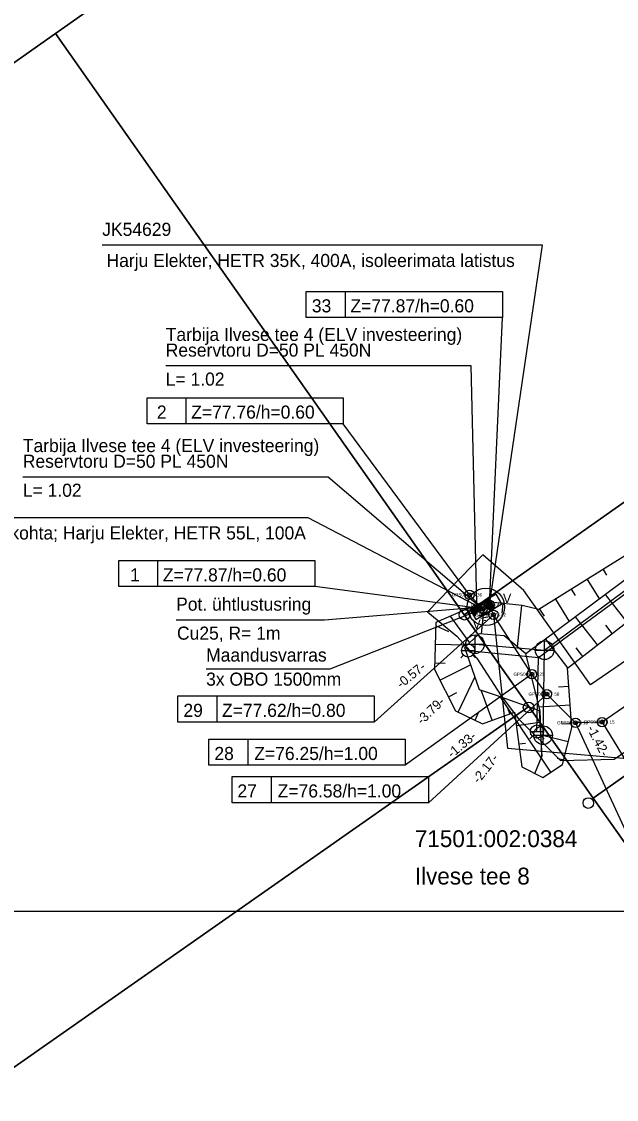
# Model space of a CAD drawing. Extents: x 593727 to 603084, y 6472047 to 6482364.
# Drawn here: x 595964.2 to 595996, y 6473948.9 to 6474006.5 of the extents above; entities that cross this region are included whole.
import ezdxf

# ---------------------------------------------------------------- set-up
doc = ezdxf.new("R2010")
doc.units = 0
for name, color, linetype in [('ELRAJATISMP', 7, 'Continuous'), ('JOONSIDE', 7, 'Continuous'), ('KKAEV', 7, 'Continuous'), ('KOORDPUNKT', 7, 'Continuous'), ('KTRASS', 7, 'Continuous'), ('MOOTKORG-EH2000', 7, 'Continuous'), ('MOOTMPUNKT', 7, 'Continuous'), ('MOOTNR', 7, 'Continuous'), ('MOOTPIIR', 7, 'Continuous'), ('MPKAABEL', 7, 'Continuous'), ('PIIR', 7, 'Continuous'), ('PIIRIMLEITUD', 7, 'Continuous'), ('RELJEEF', 7, 'Continuous'), ('VKAEV', 7, 'Continuous'), ('VORMISTUS', 7, 'Continuous'), ('VTRASS', 7, 'Continuous')]:
    doc.layers.add(name, color=color, linetype=linetype)

msp = doc.modelspace()

# ---------------------------------------------------------------- linework, layer by layer
at = {"layer": 'ELRAJATISMP'}
for p, q in [((595989.191, 6473975.644), (595988.163, 6473975.036)), ((595988.91, 6473975.459), (595988.171, 6473975.022)), ((595988.39, 6473974.652), (595988.931, 6473975.491)), ((595989.559, 6473975.862), (595988.531, 6473975.254)), ((595988.726, 6473974.676), (595989.268, 6473975.514)), ((595988.928, 6473975.489), (595989.232, 6473974.975)), ((595989.169, 6473975.614), (595988.936, 6473975.476)), ((595989.177, 6473975.601), (595988.943, 6473975.463)), ((595989.185, 6473975.588), (595988.951, 6473975.45)), ((595989.188, 6473975.582), (595988.954, 6473975.444)), ((595989.196, 6473975.57), (595988.962, 6473975.431)), ((595989.203, 6473975.557), (595988.97, 6473975.418)), ((595989.211, 6473975.544), (595988.977, 6473975.406)), ((595989.219, 6473975.531), (595988.985, 6473975.393)), ((595989.226, 6473975.518), (595988.993, 6473975.38)), ((595989.234, 6473975.505), (595989, 6473975.367)), ((595989.241, 6473975.492), (595989.008, 6473975.354)), ((595989.249, 6473975.479), (595989.015, 6473975.341)), ((595989.257, 6473975.466), (595989.023, 6473975.328)), ((595989.263, 6473975.456), (595989.029, 6473975.318)), ((595989.162, 6473975.627), (595989.465, 6473975.113)), ((595989.495, 6473975.131), (595989.191, 6473975.644)), ((595989.863, 6473975.348), (595989.559, 6473975.862)), ((595988.163, 6473975.036), (595988.466, 6473974.522)), ((595988.89, 6473975.427), (595988.18, 6473975.007)), ((595988.869, 6473975.396), (595988.188, 6473974.993)), ((595988.849, 6473975.364), (595988.197, 6473974.978)), ((595988.829, 6473975.332), (595988.206, 6473974.964)), ((595988.808, 6473975.3), (595988.214, 6473974.949)), ((595988.788, 6473975.269), (595988.223, 6473974.935)), ((595988.767, 6473975.237), (595988.231, 6473974.92)), ((595988.747, 6473975.205), (595988.24, 6473974.906)), ((595988.726, 6473975.174), (595988.248, 6473974.891)), ((595988.706, 6473975.142), (595988.257, 6473974.877)), ((595988.685, 6473975.11), (595988.266, 6473974.862)), ((595988.665, 6473975.079), (595988.274, 6473974.848)), ((595988.644, 6473975.047), (595988.283, 6473974.833)), ((595988.624, 6473975.015), (595988.291, 6473974.819)), ((595988.603, 6473974.984), (595988.3, 6473974.804)), ((595988.583, 6473974.952), (595988.309, 6473974.79)), ((595988.563, 6473974.92), (595988.317, 6473974.775)), ((595988.542, 6473974.888), (595988.326, 6473974.761)), ((595988.466, 6473974.522), (595989.495, 6473975.131)), ((595988.531, 6473975.254), (595988.835, 6473974.74)), ((595988.835, 6473974.74), (595989.863, 6473975.348)), ((595989.27, 6473975.443), (595989.037, 6473975.305)), ((595989.278, 6473975.43), (595989.044, 6473975.292)), ((595989.286, 6473975.417), (595989.052, 6473975.279)), ((595989.292, 6473975.407), (595989.058, 6473975.269)), ((595989.299, 6473975.394), (595989.066, 6473975.256)), ((595989.307, 6473975.381), (595989.073, 6473975.243)), ((595989.315, 6473975.368), (595989.081, 6473975.23)), ((595989.321, 6473975.358), (595989.087, 6473975.22)), ((595989.328, 6473975.345), (595989.095, 6473975.207)), ((595989.336, 6473975.332), (595989.102, 6473975.194)), ((595989.344, 6473975.319), (595989.11, 6473975.181)), ((595989.35, 6473975.309), (595989.116, 6473975.171)), ((595989.357, 6473975.296), (595989.124, 6473975.158)), ((595989.365, 6473975.283), (595989.131, 6473975.145)), ((595989.373, 6473975.27), (595989.139, 6473975.132)), ((595989.379, 6473975.26), (595989.145, 6473975.122)), ((595989.386, 6473975.247), (595989.153, 6473975.109)), ((595989.394, 6473975.234), (595989.16, 6473975.096)), ((595989.401, 6473975.221), (595989.168, 6473975.083)), ((595989.408, 6473975.211), (595989.174, 6473975.073)), ((595989.415, 6473975.198), (595989.182, 6473975.06)), ((595989.423, 6473975.185), (595989.189, 6473975.047)), ((595989.43, 6473975.173), (595989.197, 6473975.034)), ((595989.437, 6473975.162), (595989.203, 6473975.024)), ((595989.444, 6473975.149), (595989.21, 6473975.011)), ((595989.452, 6473975.136), (595989.218, 6473974.998)), ((595989.459, 6473975.124), (595989.226, 6473974.985)), ((595988.522, 6473974.857), (595988.334, 6473974.746)), ((595988.501, 6473974.825), (595988.343, 6473974.731)), ((595988.481, 6473974.793), (595988.351, 6473974.717)), ((595988.46, 6473974.762), (595988.36, 6473974.702)), ((595988.44, 6473974.73), (595988.369, 6473974.688)), ((595988.419, 6473974.698), (595988.377, 6473974.673)), ((595988.399, 6473974.667), (595988.386, 6473974.659))]:
    msp.add_line(p, q, dxfattribs=at)
for points in [[(595989.197, 6473975.301), (595992.049, 6473994.528), (595968.475, 6473994.528)], [(595988.829, 6473975.083), (595979.506, 6473979.96), (595959.794, 6473979.96)]]:
    msp.add_lwpolyline(points, dxfattribs=at)
at = {"layer": 'KKAEV'}
for p, q in [((595987.929, 6473973.193), (595988.929, 6473973.193)), ((595988.429, 6473972.693), (595988.429, 6473973.693)), ((595992.154, 6473972.373), (595992.154, 6473973.373)), ((595991.654, 6473972.873), (595992.654, 6473972.873)), ((595992.07, 6473967.831), (595992.07, 6473968.831)), ((595991.57, 6473968.331), (595992.57, 6473968.331))]:
    msp.add_line(p, q, dxfattribs=at)
for centre in [(595988.429, 6473973.193), (595992.154, 6473972.873), (595992.07, 6473968.331)]:
    msp.add_circle(centre, 0.5, dxfattribs=at)
at = {"layer": 'KOORDPUNKT'}
for points in [[(595989.197, 6473975.301), (595989.897, 6473990.658), (595979.397, 6473990.658), (595979.397, 6473992.058), (595989.897, 6473992.058), (595989.897, 6473990.658)], [(595981.497, 6473990.658), (595981.497, 6473992.058)], [(595988.134, 6473975.836), (595981.376, 6473984.977), (595970.876, 6473984.977), (595970.876, 6473986.377), (595981.376, 6473986.377), (595981.376, 6473984.977)], [(595972.976, 6473984.977), (595972.976, 6473986.377)], [(595988.829, 6473975.083), (595979.858, 6473976.273), (595969.358, 6473976.273), (595969.358, 6473977.673), (595979.858, 6473977.673), (595979.858, 6473976.273)], [(595971.458, 6473976.273), (595971.458, 6473977.673)], [(595989.417, 6473974.773), (595983.023, 6473969.029), (595972.523, 6473969.029), (595972.523, 6473970.429), (595983.023, 6473970.429), (595983.023, 6473969.029)], [(595991.471, 6473971.588), (595984.682, 6473966.723), (595974.182, 6473966.723), (595974.182, 6473968.123), (595984.682, 6473968.123), (595984.682, 6473966.723)], [(595974.623, 6473969.029), (595974.623, 6473970.429)], [(595992.272, 6473970.526), (595985.932, 6473964.721), (595975.432, 6473964.721), (595975.432, 6473966.121), (595985.932, 6473966.121), (595985.932, 6473964.721)], [(595993.808, 6473968.997), (595997.076, 6473961.946), (596007.576, 6473961.946), (596007.576, 6473963.346), (595997.076, 6473963.346), (595997.076, 6473961.946)], [(595995.228, 6473969.033), (595998.331, 6473963.948), (596008.831, 6473963.948), (596008.831, 6473965.348), (595998.331, 6473965.348), (595998.331, 6473963.948)], [(595976.282, 6473966.723), (595976.282, 6473968.123)], [(595977.532, 6473964.721), (595977.532, 6473966.121)]]:
    msp.add_lwpolyline(points, dxfattribs=at)
for centre, radius in [((595988.134, 6473975.836), 0.25), ((595988.134, 6473975.836), 0.025), ((595988.134, 6473975.836), 0.0221), ((595988.134, 6473975.836), 0.0191), ((595988.134, 6473975.836), 0.0161), ((595988.134, 6473975.836), 0.0132), ((595988.134, 6473975.836), 0.0102), ((595988.134, 6473975.836), 0.00726), ((595988.134, 6473975.836), 0.0043), ((595989.197, 6473975.301), 0.25), ((595988.829, 6473975.083), 0.25), ((595988.829, 6473975.083), 0.025), ((595988.829, 6473975.083), 0.0221), ((595988.829, 6473975.083), 0.0191), ((595988.829, 6473975.083), 0.0161), ((595988.829, 6473975.083), 0.0132), ((595988.829, 6473975.083), 0.0102), ((595988.829, 6473975.083), 0.00726), ((595988.829, 6473975.083), 0.0043), ((595989.417, 6473974.773), 0.25), ((595989.197, 6473975.301), 0.025), ((595989.197, 6473975.301), 0.0221), ((595989.197, 6473975.301), 0.0191), ((595989.197, 6473975.301), 0.0161), ((595989.197, 6473975.301), 0.0132), ((595989.197, 6473975.301), 0.0102), ((595989.197, 6473975.301), 0.00726), ((595989.197, 6473975.301), 0.0043), ((595989.417, 6473974.773), 0.025), ((595989.417, 6473974.773), 0.0221), ((595989.417, 6473974.773), 0.0191), ((595989.417, 6473974.773), 0.0161), ((595989.417, 6473974.773), 0.0132), ((595989.417, 6473974.773), 0.0102), ((595989.417, 6473974.773), 0.00726), ((595989.417, 6473974.773), 0.0043), ((595991.471, 6473971.588), 0.25), ((595991.471, 6473971.588), 0.025), ((595991.471, 6473971.588), 0.0221), ((595991.471, 6473971.588), 0.0191), ((595991.471, 6473971.588), 0.0161), ((595991.471, 6473971.588), 0.0132), ((595991.471, 6473971.588), 0.0102), ((595991.471, 6473971.588), 0.00726), ((595991.471, 6473971.588), 0.0043), ((595992.272, 6473970.526), 0.25), ((595992.272, 6473970.526), 0.025), ((595992.272, 6473970.526), 0.0221), ((595992.272, 6473970.526), 0.0191), ((595992.272, 6473970.526), 0.0161), ((595992.272, 6473970.526), 0.0132), ((595992.272, 6473970.526), 0.0102), ((595992.272, 6473970.526), 0.00726), ((595992.272, 6473970.526), 0.0043), ((595993.808, 6473968.997), 0.25), ((595995.228, 6473969.033), 0.25), ((595993.808, 6473968.997), 0.025), ((595993.808, 6473968.997), 0.0221), ((595993.808, 6473968.997), 0.0191), ((595993.808, 6473968.997), 0.0161), ((595993.808, 6473968.997), 0.0132), ((595993.808, 6473968.997), 0.0102), ((595993.808, 6473968.997), 0.00726), ((595993.808, 6473968.997), 0.0043), ((595995.228, 6473969.033), 0.025), ((595995.228, 6473969.033), 0.0221), ((595995.228, 6473969.033), 0.0191), ((595995.228, 6473969.033), 0.0161), ((595995.228, 6473969.033), 0.0132), ((595995.228, 6473969.033), 0.0102), ((595995.228, 6473969.033), 0.00726), ((595995.228, 6473969.033), 0.0043)]:
    msp.add_circle(centre, radius, dxfattribs=at)
at = {"layer": 'KTRASS'}
msp.add_line((595992.07, 6473968.331), (595992.154, 6473972.873), dxfattribs=at)
msp.add_lwpolyline([(595988.429, 6473973.193), (595992.154, 6473972.873), (596021.268, 6473994.477), (596027.413, 6473985.696)], dxfattribs=at)
at = {"layer": 'MOOTMPUNKT'}
for centre in [(595988.134, 6473975.836), (595988.829, 6473975.083), (595989.197, 6473975.301), (595989.417, 6473974.773), (595991.471, 6473971.588), (595992.272, 6473970.526), (595995.228, 6473969.033), (595993.808, 6473968.997)]:
    msp.add_circle(centre, 0.1, dxfattribs=at)
at = {"layer": 'MOOTPIIR'}
msp.add_lwpolyline([(595996.874, 6473972.574), (595994.603, 6473971.027), (595991.042, 6473976.073), (595988.852, 6473977.98), (595985.881, 6473974.923), (595987.451, 6473973.627), (595988.531, 6473972.457), (595989.83, 6473970.442), (595990.761, 6473969.209), (595993.003, 6473966.976), (595995.868, 6473967.049), (595999.206, 6473969.324)], dxfattribs=at)
at = {"layer": 'MPKAABEL'}
for q in [(595988.039, 6473975.735), (595988.134, 6473975.836)]:
    msp.add_line((595988.829, 6473975.083), q, dxfattribs=at)
for points in [[(595997.222, 6474041.549), (595998.968, 6474037.996), (596003.482, 6474031.514), (596011.528, 6474019.578), (596019.439, 6474008.315), (596026.978, 6473997.816), (596029.342, 6473994.732), (596029.364, 6473993.819), (596026.896, 6473991.824), (596022.401, 6473988.312), (596009.78, 6473979.811), (596004.261, 6473975.645), (595998.04, 6473970.949), (595995.228, 6473969.033), (595993.808, 6473968.997), (595992.272, 6473970.526), (595991.471, 6473971.588), (595989.417, 6473974.773), (595989.197, 6473975.301)], [(595988.532, 6473975.404), (595988.218, 6473988.071), (595971.874, 6473988.071)], [(595988.412, 6473975.427), (595980.568, 6473982.128), (595964.224, 6473982.128)], [(596004.261, 6473975.645), (595998.04, 6473970.949), (595995.228, 6473969.033), (595993.808, 6473968.997), (595992.272, 6473970.526), (595991.471, 6473971.588), (595989.417, 6473974.773)], [(595989.013, 6473975.192), (595980.372, 6473974.487), (595972.43, 6473974.487)], [(595974.036, 6473971.877), (595980.671, 6473971.877), (595988.829, 6473975.083)], [(595988.829, 6473975.083), (595988.896, 6473974.751)], [(595989.208, 6473974.814), (595988.585, 6473974.688)], [(595989.106, 6473974.641), (595988.746, 6473974.567)], [(595989.005, 6473974.467), (595988.907, 6473974.447)], [(595989.417, 6473974.773), (595990.171, 6473967.629), (596000.288, 6473966.757)]]:
    msp.add_lwpolyline(points, dxfattribs=at)
msp.add_circle((595989.013, 6473975.192), 1, dxfattribs=at)
at = {"layer": 'PIIR'}
for points in [[(595920.02, 6474021.81), (595923.45, 6474023.94), (595974.94, 6474056.4), (595995.81, 6474026.85), (595965.97, 6474005.85), (595935.81, 6473984.63), (595931.46, 6473994.7)], [(595965.97, 6474005.85), (595995.81, 6474026.85), (596019.09, 6473993.75), (595999.1, 6473979.65), (595997.67, 6473981.68), (595987.85, 6473974.77)], [(595935.81, 6473984.63), (595965.97, 6474005.85), (595987.85, 6473974.77), (595991.31, 6473969.86), (595963.77, 6473950.58), (595962.03, 6473949.48), (595953.34, 6473961.05)], [(595994.75, 6473964.97), (596004.56, 6473971.88), (596003.14, 6473973.91), (596023.13, 6473988.02), (596046.52, 6473955.01), (596016.68, 6473934.04)], [(595962.03, 6473949.48), (595963.77, 6473950.58), (595991.31, 6473969.86), (595994.75, 6473964.97), (596016.68, 6473934.04), (595975.1, 6473904.62), (595970.53, 6473901.86), (595972.52, 6473915.54), (595965.11, 6473943.08)]]:
    msp.add_lwpolyline(points, close=True, dxfattribs=at)
msp.add_lwpolyline([(596066.57, 6473926.31), (596046.52, 6473955.01), (596023.13, 6473988.02), (596003.14, 6473973.91), (596004.56, 6473971.88), (595994.75, 6473964.97), (595991.31, 6473969.86), (595987.85, 6473974.77), (595997.67, 6473981.68), (595999.1, 6473979.65), (596019.09, 6473993.75), (595995.81, 6474026.85), (595974.94, 6474056.4)], dxfattribs=at)
at = {"layer": 'PIIRIMLEITUD'}
for centre in [(595987.867, 6473974.774), (595991.298, 6473969.811), (595994.494, 6473964.703)]:
    msp.add_circle(centre, 0.285, dxfattribs=at)
at = {"layer": 'RELJEEF'}
for p, q in [((595995.282, 6473977.189), (595995.465, 6473976.895)), ((595994.433, 6473976.661), (595995.087, 6473975.61)), ((595993.584, 6473976.133), (595993.793, 6473975.796)), ((595988.931, 6473975.481), (595988.75, 6473973.747)), ((595992.735, 6473975.604), (595993.477, 6473974.412)), ((595996.567, 6473974.378), (595995.421, 6473975.859)), ((595988.012, 6473975.092), (595988.191, 6473974.68)), ((595989.925, 6473975.377), (595989.872, 6473974.862)), ((595990.92, 6473975.273), (595990.689, 6473973.063)), ((595991.886, 6473975.076), (595992.122, 6473974.697)), ((595987.095, 6473974.694), (595988.137, 6473973.272)), ((595994.985, 6473973.154), (595993.816, 6473974.665)), ((595986.32, 6473974.2), (595987.006, 6473973.88)), ((595995.776, 6473973.766), (595995.429, 6473974.215)), ((595986.294, 6473973.201), (595988.014, 6473973.156)), ((595993.403, 6473971.93), (595992.212, 6473973.471)), ((595994.194, 6473972.542), (595993.84, 6473973)), ((595986.268, 6473972.201), (595986.837, 6473972.186)), ((595986.549, 6473971.27), (595988.184, 6473972.099)), ((595987.526, 6473969.561), (595988.415, 6473971.437)), ((595993.451, 6473970.941), (595992.902, 6473970.904)), ((595987.001, 6473970.378), (595987.456, 6473970.609)), ((595989.352, 6473969.128), (595988.761, 6473970.736)), ((595992.483, 6473966.346), (595989.775, 6473970.397)), ((595990.29, 6473969.474), (595990.197, 6473969.729)), ((595993.519, 6473969.944), (595991.864, 6473969.831)), ((595988.429, 6473969.132), (595988.64, 6473969.577)), ((595990.646, 6473968.852), (595991.902, 6473969.02)), ((595993.588, 6473968.946), (595993.095, 6473968.912)), ((595993.417, 6473967.969), (595991.966, 6473968.329)), ((595990.778, 6473967.861), (595991.134, 6473967.908)), ((595991.625, 6473966.285), (595992.013, 6473967.189)), ((595993.176, 6473966.999), (595992.826, 6473967.086))]:
    msp.add_line(p, q, dxfattribs=at)
for points in [[(596021.957, 6473994.214), (596017.907, 6473998.448), (596016.871, 6473997.981), (596016.803, 6473996.451), (596017.612, 6473994.709), (596015.695, 6473992.145), (596006.538, 6473985.945), (595998.808, 6473979.384), (595991.844, 6473975.05), (595990.953, 6473975.27), (595988.912, 6473975.483), (595986.324, 6473974.36), (595986.259, 6473971.842), (595987.38, 6473969.63), (595988.837, 6473968.939), (595990.55, 6473969.569), (595990.941, 6473966.644), (595992.055, 6473966.06), (595993.12, 6473966.772), (595993.603, 6473968.719), (595993.385, 6473971.916), (596008.142, 6473983.332), (596016.283, 6473990.523), (596021.957, 6473994.214)], [(596018.28, 6473997.118), (596020.283, 6473993.877), (596016.041, 6473991.337), (596007.647, 6473984.956), (595991.153, 6473972.683), (595989.99, 6473973.637), (595988.649, 6473973.756), (595987.864, 6473973.014), (595988.647, 6473970.773), (595989.557, 6473970.474), (595991.864, 6473969.657), (595992.013, 6473967.189), (595991.913, 6473969.636), (595991.153, 6473972.683)]]:
    msp.add_lwpolyline(points, dxfattribs=at)
at = {"layer": 'VKAEV'}
for p, q in [((595987.817, 6473972.611), (595987.677, 6473972.471)), ((595987.714, 6473972.858), (595988.414, 6473972.858)), ((595988.311, 6473972.611), (595988.451, 6473972.471)), ((595991.499, 6473968.281), (595991.359, 6473968.141)), ((595991.396, 6473968.528), (595992.096, 6473968.528)), ((595991.993, 6473968.281), (595992.133, 6473968.141))]:
    msp.add_line(p, q, dxfattribs=at)
for centre in [(595988.064, 6473972.858), (595991.746, 6473968.528)]:
    msp.add_circle(centre, 0.35, dxfattribs=at)
at = {"layer": 'VORMISTUS'}
msp.add_lwpolyline([(595935.65, 6473958.907), (595935.65, 6474102.407), (596133.15, 6474102.407), (596133.15, 6473958.907)], close=True, dxfattribs=at)
at = {"layer": 'VTRASS'}
msp.add_line((595988.064, 6473972.858), (595991.823, 6473972.49), dxfattribs=at)
msp.add_lwpolyline([(595991.746, 6473968.528), (595991.823, 6473972.49), (596021.07, 6473993.982), (596027.071, 6473985.453)], dxfattribs=at)

# ---------------------------------------------------------------- texts
at = {"layer": 'ELRAJATISMP'}
for s, height, p in [('JK54629', 0.7, (595968.475, 6473995.028)), ('Harju Elekter, HETR 35K, 400A, isoleerimata latistus', 0.7, (595968.705, 6473993.363)), ('2 arvestikohta; Harju Elekter, HETR 55L, 100A', 0.7, (595960.023, 6473978.795)), ('V', 0.5, (595989.924, 6473975.395)), ('V', 0.5, (595988.291, 6473974.015))]:
    msp.add_text(s, height=height, dxfattribs=at).set_placement(p)
at = {"layer": 'JOONSIDE'}
for s, rotation, p in [('-0.57-', 38.89009, (595984.474, 6473970.804)), ('-3.79-', 43.87311, (595985.586, 6473968.855)), ('-1.42-', 297.49723, (595994.399, 6473968.693)), ('-1.33-', 39.87079, (595987.199, 6473967.081)), ('-2.17-', 51.72896, (595988.636, 6473965.715))]:
    msp.add_text(s, height=0.5, rotation=rotation, dxfattribs=at).set_placement(p)
at = {"layer": 'KOORDPUNKT'}
for s, p in [('33', (595979.695, 6473990.938)), ('Z=77.87/h=0.60', (595981.76, 6473990.938)), ('2', (595971.401, 6473985.257)), ('Z=77.76/h=0.60', (595973.238, 6473985.257)), ('1', (595969.97, 6473976.553)), ('Z=77.87/h=0.60', (595971.72, 6473976.553)), ('29', (595972.821, 6473969.309)), ('Z=77.62/h=0.80', (595974.886, 6473969.309)), ('28', (595974.479, 6473967.003)), ('Z=76.25/h=1.00', (595976.614, 6473967.003)), ('27', (595975.712, 6473965.001)), ('Z=76.58/h=1.00', (595977.865, 6473965.001))]:
    msp.add_text(s, height=0.7, dxfattribs=at).set_placement(p)
at = {"layer": 'MOOTKORG-EH2000'}
for s, p in [(' 78.36', (595988.134, 6473975.749)), (' 78.47', (595988.829, 6473974.996)), (' 78.47', (595989.197, 6473975.214)), (' 78.42', (595989.417, 6473974.686)), (' 77.25', (595991.471, 6473971.5)), (' 77.58', (595992.272, 6473970.438)), (' 78.15', (595995.228, 6473968.945)), (' 78.19', (595993.808, 6473968.909))]:
    msp.add_text(s, height=0.175, dxfattribs=at).set_placement(p)
at = {"layer": 'MOOTNR'}
for s, p in [('GPS0001 ', (595987.189, 6473975.749)), ('GPS0005 ', (595987.849, 6473974.996)), ('GPS0004 ', (595988.199, 6473975.214)), ('GPS0002 ', (595988.429, 6473974.686)), ('GPS0006 ', (595990.491, 6473971.5)), ('GPS0007 ', (595991.292, 6473970.438)), ('GPS0009 ', (595994.248, 6473968.945)), ('GPS0008 ', (595992.828, 6473968.909))]:
    msp.add_text(s, height=0.175, dxfattribs=at).set_placement(p)
at = {"layer": 'MPKAABEL'}
for s, p in [('Tarbija Ilvese tee 4 (ELV investeering)', (595971.874, 6473989.408)), ('Reservtoru D=50 PL 450N', (595971.874, 6473988.571)), ('L= 1.02', (595971.874, 6473987.021)), ('Tarbija Ilvese tee 4 (ELV investeering)', (595964.224, 6473983.466)), ('Reservtoru D=50 PL 450N', (595964.224, 6473982.628)), ('L= 1.02', (595964.224, 6473981.078)), ('Pot. ühtlustusring', (595972.43, 6473974.987)), ('Cu25, R= 1m', (595972.477, 6473973.437)), ('Maandusvarras', (595974.036, 6473972.268)), ('3x OBO 1500mm', (595974.036, 6473970.977))]:
    msp.add_text(s, height=0.7, dxfattribs=at).set_placement(p)
at = {"layer": 'PIIR'}
for s, p in [('71501:002:0384', (595985.206, 6473962.347)), ('Ilvese tee 8', (595985.206, 6473960.347))]:
    msp.add_text(s, height=0.9, dxfattribs=at).set_placement(p)

doc.saveas('drawing.dxf')
